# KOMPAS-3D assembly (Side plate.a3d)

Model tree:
1. X Axis
2. Y Axis
3. Z Axis
4. Origin
5. Linear Pattern:1  (labels: Instance ( 2, 1 );; Instance ( 3, 1 );; Instance ( 4, 1 );; Instance ( 5, 1 );)
     Included Angle = 90; N 2 = 1; Spacing 2 = 10; Orientation = 2

Expressions: L+(2*Delta)
Referenced files in D:\Documents and Settings\kashirsky\Рабочий стол\My sample\: skrzynia1.a3d|N, skrzynia1.a3d|H, Base plate.m3d|Thick, skrzynia1.a3d|W, skrzynia1.a3d|Delta, Side plate.m3d, rail2.m3d, Side plate.a3d, Side plate.spw, skrzynia1.a3d, skrzynia1.spw, Box.cdw
Referenced files in C:\Work\01 К О М П А С\Модели примеры\2009_04_For_Poland_AXAPACK\My sample\: skrzynia1.a3d, Base plate.m3d
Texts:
  Plate of side
  Wood (15% moisture content)
  Three Point Plane
  Plane at Angle
  Line and Point Plane
  Axis through Two Vertices
  Axis of Feature
  Axis of Conical Surface
  Axis through Edge
  Trim by Surface
  Trim by Sketch
  Intersection Axis of Two Planes
  Two Line Plane
  Line and Face Plane
  Pattern by Sample
  Point in CM
  Feature with No History
  Linear Dimension from Line to Point
  Surface Finish Symbol
  Geometric Tolerance Symbol
  Leader #1
  Leader #2
  Leader #3
  Shape Deviations and Datum
  Node point number
  Mark of coordination axis
  Node point designation
  Mark/Reference designation with leader
  Mark/reference designation on line
  Mark/Reference designation without leader
  (SP_W-BP_thickness)-100
  Plate 02
  Rail 02
  Instance ( 2, 1 );
  Instance ( 3, 1 );
  Instance ( 4, 1 );
  Instance ( 5, 1 );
